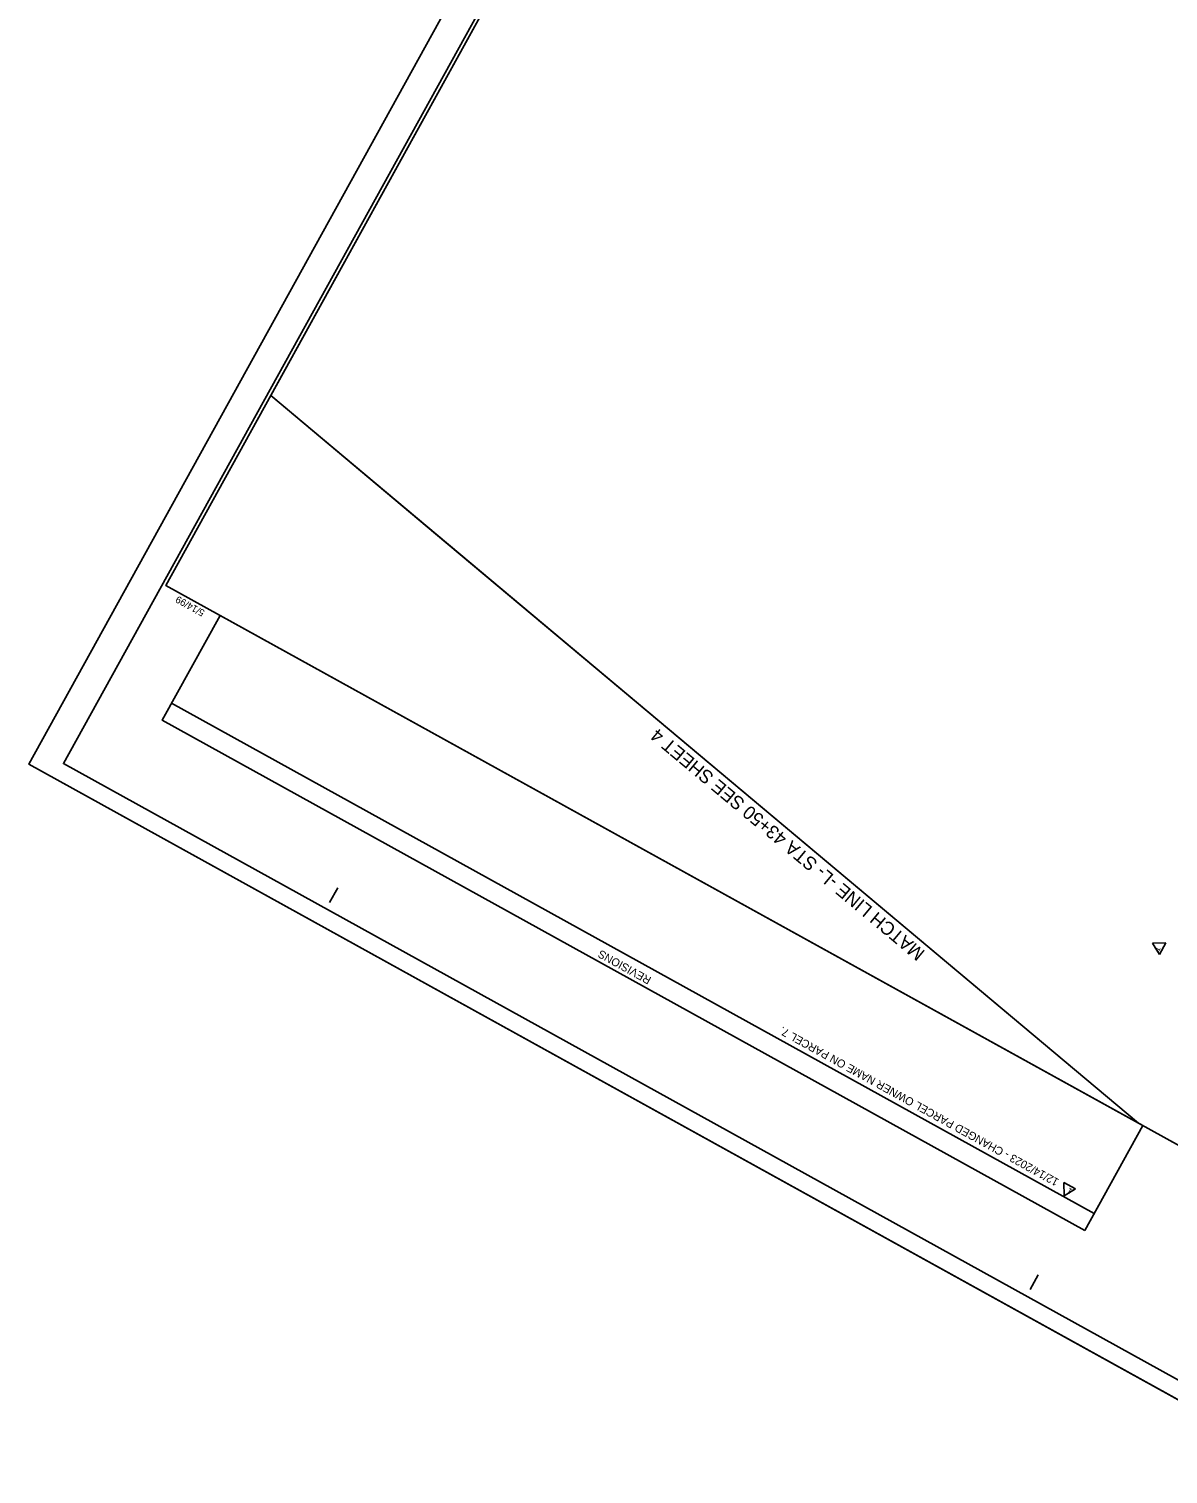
# Model space of a CAD drawing. Extents: x 2176096 to 2177873, y 76962 to 79129.
# Drawn here: x 2176096 to 2176950, y 76962 to 78046 of the extents above; entities that cross this region are included whole.
import ezdxf

# ---------------------------------------------------------------- set-up
doc = ezdxf.new("R2010")
doc.units = 0
for name, color, linetype in [('CTL Primary Horizontal and Vertical CELL', 7, 'Continuous'), ('CTL Primary Horizontal CELL', 7, 'Continuous'), ('CTL Primary Horizontal Cogo Elevation', 7, 'Continuous'), ('CTL Primary Horizontal Cogo Number', 7, 'Continuous'), ('Exist Other Culture Sign Cogo Point CELL', 7, 'Continuous'), ('Exist Structure Minor Pipes RCP 18 Inch', 7, 'Continuous'), ('Exist Vegetation Tree CELL', 7, 'Continuous')]:
    doc.layers.add(name, color=color, linetype=linetype)

msp = doc.modelspace()

# ---------------------------------------------------------------- linework, layer by layer
at = {"layer": 'CTL Primary Horizontal and Vertical CELL'}
msp.add_lwpolyline([(2176762, 78648.7), (2176276.9, 77771), (2176400.5, 77667.3), (2176500.7, 77583.3), (2176559.2, 77534.4), (2176927.7, 77225.4), (2177117.2, 77120.7), (2177568.3, 77937), (2177830.4, 78411.2), (2177842.7, 78433.6), (2177075.6, 78857.5), (2176978.9, 78682.4), (2176907.9, 78721.6), (2176842.9, 78604)], close=True, dxfattribs=at)
at = {"layer": 'CTL Primary Horizontal CELL'}
msp.add_lwpolyline([(2176927.6, 78953.6), (2176121.5, 77495), (2177045, 76984.7), (2177851, 78443.3)], close=True, dxfattribs=at)
at = {"layer": 'CTL Primary Horizontal Cogo Elevation'}
for p, q in [((2176910.1, 78968.4), (2176095.6, 77494.5)), ((2176095.6, 77494.5), (2177058.3, 76962.4))]:
    msp.add_line(p, q, dxfattribs=at)
at = {"layer": 'CTL Primary Horizontal Cogo Number'}
msp.add_lwpolyline([(2176910.1, 78968.4), (2176095.6, 77494.5), (2177058.3, 76962.4), (2177872.8, 78436.3)], close=True, dxfattribs=at)
at = {"layer": 'Exist Other Culture Sign Cogo Point CELL'}
for p, q in [((2176198.7, 77629.5), (2176198.7, 77629.5)), ((2176321.1, 77391), (2176327.2, 77401.9)), ((2176846.3, 77100.8), (2176852.3, 77111.7))]:
    msp.add_line(p, q, dxfattribs=at)
msp.add_lwpolyline([(2176923.7, 78941.4), (2176198.2, 77628.6), (2177117.2, 77120.7), (2177842.7, 78433.6)], close=True, dxfattribs=at)
at = {"layer": 'Exist Structure Minor Pipes RCP 18 Inch'}
for p, q in [((2176894.5, 77157.8), (2176202.5, 77540.2)), ((2176938.1, 77360.5), (2176948.2, 77360.6)), ((2176943.4, 77351.9), (2176938.1, 77360.5)), ((2176943.4, 77351.9), (2176948.2, 77360.6)), ((2176880.4, 77176.3), (2176871.7, 77181.1)), ((2176871.8, 77171), (2176871.7, 77181.1)), ((2176880.4, 77176.3), (2176871.8, 77171))]:
    msp.add_line(p, q, dxfattribs=at)
msp.add_lwpolyline([(2176887.5, 77145), (2176195.5, 77527.5), (2176238.9, 77606.1), (2176930.9, 77223.7)], close=True, dxfattribs=at)
at = {"layer": 'Exist Vegetation Tree CELL'}
msp.add_line((2176927.7, 77225.4), (2176276.9, 77771), dxfattribs=at)

# ---------------------------------------------------------------- texts
at = {"layer": 'Exist Other Culture Sign Cogo Point CELL'}
msp.add_text('5/14/99', height=5.25, rotation=151.0733, dxfattribs=at).set_placement((2176227.9, 77609.6))
at = {"layer": 'Exist Structure Minor Pipes RCP 18 Inch'}
for s, height, rotation, p in [(' 1', 4.5, 61.0733, (2176942, 77352.2)), ('REVISIONS', 6, 151.0733, (2176562.8, 77334.5)), ('  12/14/2023 - CHANGED PARCEL OWNER NAME ON PARCEL 7.', 6, 151.0733, (2176872.4, 77181)), (' 1', 4.5, 151.0733, (2176880, 77174.9))]:
    msp.add_text(s, height=height, rotation=rotation, dxfattribs=at).set_placement(p)
at = {"layer": 'Exist Vegetation Tree CELL'}
msp.add_text('MATCH LINE -L- STA 43+50 SEE SHEET 4', height=10, rotation=140.1328, dxfattribs=at).set_placement((2176768.2, 77354.1))

doc.saveas('drawing.dxf')
